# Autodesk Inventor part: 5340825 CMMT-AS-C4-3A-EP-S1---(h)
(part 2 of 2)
sketch "Sketch_51"
  geometry: L1 (0, 66.25)-(0, 58); L2 (1, 59)-(25.25, 59); L3 (28.25, 62)-(28.25, 85); L4 (28.25, 85)-(22, 85); L5 (22, 85)-(22, 65.5); L6 (21.75, 65.25)-(1, 65.25); A1 r 1 centre (1, 58) between (1, 59) and (0, 58); A2 r 3 centre (25.25, 62) between (25.25, 59) and (28.25, 62); A3 r 0.25 centre (21.75, 65.5) between (21.75, 65.25) and (22, 65.5); A4 r 1 centre (1, 66.25) between (0, 66.25) and (1, 65.25)
  constraints: 12 end point, 8 point on circle, 4 centre point
extrude "Extrusion63" cut sketch "Sketch_51" distance "d193" = 3.25; taper "d194" = 0 deg
sketch "Sketch_8"
  geometry: L1 (15, 101)-(5, 101); L2 (5, 101)-(5, 103); L3 (5, 103)-(7, 103); L4 (7, 103)-(7, 105.5); L5 (7, 105.5)-(8, 105.5); L6 (8, 105.5)-(8, 105); L7 (8, 105)-(10.133, 104.813); L8 (11.1, 101)-(5, 101); A1 r 8 centre (3.1, 101.001) between (11.1, 101) and (10.133, 104.813)
  constraints: 16 end point, 2 point on circle, 1 centre point
revolve "Revolution11" sketch "Sketch_8" stored, may be unused: angle "d195" = 360 deg
thread "Thread3" dims "d196" = 2, "d197" = 0
sketch "Sketch_9"
  geometry: A1 r 0.396 centre (-15.37, 100.209) between (-15.642, 100.497) and (-15.257, 99.83); A2 r 0.692 centre (-15.058, 99.167) between (-14.385, 99.327) and (-15.257, 99.83); A3 r 0.396 centre (-14, 99.418) between (-14.385, 99.327) and (-13.615, 99.327); A4 r 0.692 centre (-12.942, 99.167) between (-12.743, 99.83) and (-13.615, 99.327); A5 r 0.396 centre (-12.63, 100.209) between (-12.743, 99.83) and (-12.358, 100.497); A6 r 0.692 centre (-11.883, 101) between (-12.358, 101.503) and (-12.358, 100.497); A7 r 0.395 centre (-12.63, 101.791) between (-12.358, 101.503) and (-12.743, 102.17); A8 r 0.692 centre (-12.942, 102.833) between (-13.615, 102.673) and (-12.743, 102.17); A9 r 0.396 centre (-14, 102.582) between (-13.615, 102.673) and (-14.385, 102.673); A10 r 0.692 centre (-15.058, 102.833) between (-15.257, 102.17) and (-14.385, 102.673); A11 r 0.395 centre (-15.37, 101.791) between (-15.257, 102.17) and (-15.642, 101.503); A12 r 0.692 centre (-16.117, 101) between (-15.642, 100.497) and (-15.642, 101.503)
  constraints: 24 point on circle, 12 centre point
extrude "Extrusion64" cut sketch "Sketch_9" distance "d198" = 2; taper "d199" = 0 deg
sketch "Sketch_57"
  geometry: L1 (-16.27, 80.62)-(-16.27, 75.48); L2 (-15.77, 74.98)-(-13.63, 74.98); L3 (-13.13, 75.48)-(-13.13, 80.62); L4 (-13.63, 81.12)-(-15.77, 81.12); A1 r 0.5 centre (-15.77, 75.48) between (-16.27, 75.48) and (-15.77, 74.98); A2 r 0.5 centre (-13.63, 75.48) between (-13.63, 74.98) and (-13.13, 75.48); A3 r 0.5 centre (-13.63, 80.62) between (-13.13, 80.62) and (-13.63, 81.12); A4 r 0.5 centre (-15.77, 80.62) between (-15.77, 81.12) and (-16.27, 80.62)
  constraints: 8 end point, 8 point on circle, 4 centre point
extrude "Extrusion65" cut sketch "Sketch_57" distance "d200" = 2.5; taper "d201" = 0 deg
pattern_linear "Rectangular Pattern9" dims "d204" = 34.7, "d207" = 41.52024
sketch "Sketch_59"
  geometry: L1 (-1.792, 72.6)-(-1.792, 59.625); L2 (-1.292, 59.125)-(1.292, 59.125); L3 (1.792, 59.625)-(1.792, 72.6); L4 (1.292, 73.1)-(-1.292, 73.1); A1 r 0.5 centre (-1.292, 59.625) between (-1.792, 59.625) and (-1.292, 59.125); A2 r 0.5 centre (1.292, 59.625) between (1.292, 59.125) and (1.792, 59.625); A3 r 0.5 centre (1.292, 72.6) between (1.792, 72.6) and (1.292, 73.1); A4 r 0.5 centre (-1.292, 72.6) between (-1.292, 73.1) and (-1.792, 72.6)
  constraints: 8 end point, 8 point on circle, 4 centre point
extrude "Extrusion66" cut sketch "Sketch_59" distance "d208" = 4; taper "d209" = 0 deg
sketch "Sketch_61"
  geometry: L1 (148.738, -20)-(149.144, -20); L2 (149.144, -20)-(149.8, -19.031); L3 (149.8, -19.031)-(150.456, -20); L4 (150.456, -20)-(150.863, -20); L5 (150.863, -20)-(149.988, -18.719); L6 (149.988, -18.719)-(150.831, -17.5); L7 (150.831, -17.5)-(150.425, -17.5); L8 (150.425, -17.5)-(149.8, -18.438); L9 (149.8, -18.438)-(149.175, -17.5); L10 (149.175, -17.5)-(148.769, -17.5); L11 (148.769, -17.5)-(149.613, -18.719); L12 (149.613, -18.719)-(148.738, -20)
  constraints: 24 end point
extrude "Extrusion67" cut sketch "Sketch_61" distance "d210" = 2; taper "d211" = 0 deg
sketch "Sketch_60"
  geometry: L1 (146.625, -19.688)-(146.625, -20); L2 (146.625, -20)-(148.406, -20); L3 (148.406, -20)-(148.406, -17.5); L4 (148.406, -17.5)-(148.062, -17.5); L5 (148.062, -17.5)-(148.062, -18.625); L6 (148.062, -18.625)-(146.75, -18.625); L7 (146.75, -18.625)-(146.75, -18.938); L8 (146.75, -18.938)-(148.062, -18.938); L9 (148.062, -18.938)-(148.062, -19.688); L10 (148.062, -19.688)-(146.625, -19.688)
  constraints: 20 end point
extrude "Extrusion68" cut sketch "Sketch_60" distance "d212" = 2; taper "d213" = 0 deg
sketch "Pattern_13_SKETCH_1"
  geometry: L1 (131.938, -20)-(132.344, -20); L2 (132.344, -20)-(133, -19.031); L3 (133, -19.031)-(133.656, -20); L4 (133.656, -20)-(134.062, -20); L5 (134.062, -20)-(133.188, -18.719); L6 (133.188, -18.719)-(134.031, -17.5); L7 (134.031, -17.5)-(133.625, -17.5); L8 (133.625, -17.5)-(133, -18.438); L9 (133, -18.438)-(132.375, -17.5); L10 (132.375, -17.5)-(131.969, -17.5); L11 (131.969, -17.5)-(132.812, -18.719); L12 (132.812, -18.719)-(131.938, -20)
  constraints: 24 end point
sketch "Pattern_13_SKETCH_2"
  geometry: L1 (99.938, -20)-(100.344, -20); L2 (100.344, -20)-(101, -19.031); L3 (101, -19.031)-(101.656, -20); L4 (101.656, -20)-(102.062, -20); L5 (102.062, -20)-(101.188, -18.719); L6 (101.188, -18.719)-(102.031, -17.5); L7 (102.031, -17.5)-(101.625, -17.5); L8 (101.625, -17.5)-(101, -18.438); L9 (101, -18.438)-(100.375, -17.5); L10 (100.375, -17.5)-(99.969, -17.5); L11 (99.969, -17.5)-(100.812, -18.719); L12 (100.812, -18.719)-(99.938, -20)
  constraints: 24 end point
sketch "Pattern_13_SKETCH_3"
  geometry: L1 (98.937, 20)-(99.344, 20); L2 (99.344, 20)-(100, 20.969); L3 (100, 20.969)-(100.656, 20); L4 (100.656, 20)-(101.062, 20); L5 (101.062, 20)-(100.187, 21.281); L6 (100.187, 21.281)-(101.031, 22.5); L7 (101.031, 22.5)-(100.625, 22.5); L8 (100.625, 22.5)-(100, 21.562); L9 (100, 21.562)-(99.375, 22.5); L10 (99.375, 22.5)-(98.969, 22.5); L11 (98.969, 22.5)-(99.812, 21.281); L12 (99.812, 21.281)-(98.937, 20)
  constraints: 24 end point
sketch "Pattern_13_SKETCH_4"
  geometry: L1 (66.938, 20)-(67.344, 20); L2 (67.344, 20)-(68, 20.969); L3 (68, 20.969)-(68.656, 20); L4 (68.656, 20)-(69.062, 20); L5 (69.062, 20)-(68.188, 21.281); L6 (68.188, 21.281)-(69.031, 22.5); L7 (69.031, 22.5)-(68.625, 22.5); L8 (68.625, 22.5)-(68, 21.562); L9 (68, 21.562)-(67.375, 22.5); L10 (67.375, 22.5)-(66.969, 22.5); L11 (66.969, 22.5)-(67.812, 21.281); L12 (67.812, 21.281)-(66.938, 20)
  constraints: 24 end point
extrude "Extrusion69" cut sketch "Pattern_13_SKETCH_1" distance "d214" = 2; taper "d215" = 0 deg
extrude "Extrusion70" cut sketch "Pattern_13_SKETCH_2" distance "d216" = 2; taper "d217" = 0 deg
extrude "Extrusion71" cut sketch "Pattern_13_SKETCH_3" distance "d218" = 2; taper "d219" = 0 deg
extrude "Extrusion72" cut sketch "Pattern_13_SKETCH_4" distance "d220" = 2; taper "d221" = 0 deg
pattern_linear "Rectangular Pattern10" dims "d224" = 16.90625, "d227" = 0
sketch "Sketch_64"
  geometry: L1 (145, -17.85)-(145.325, -17.85); L2 (145.325, -17.85)-(145.325, -20); L3 (145.325, -20)-(145.675, -20); L4 (145.675, -20)-(146, -19.5); L5 (146, -19.5)-(146, -19); L6 (146, -19)-(145.675, -19.5); L7 (145.675, -19.5)-(145.675, -17.85); L8 (145.675, -17.85)-(146, -17.85); L9 (146, -17.85)-(146, -17.5); L10 (146, -17.5)-(145, -17.5); L11 (145, -17.5)-(145, -17.85)
  constraints: 22 end point
extrude "Extrusion73" cut sketch "Sketch_64" distance "d228" = 2; taper "d229" = 0 deg
sketch "Sketch_65"
  geometry: L1 (129.25, -19.25)-(128.9, -19.25); L2 (128.224, -18.96)-(129.25, -17.983); L3 (129.25, -17.983)-(129.25, -17.5); L4 (129.25, -17.5)-(127.75, -17.5); L5 (127.75, -17.5)-(127.75, -17.85); L6 (127.75, -17.85)-(128.882, -17.85); L7 (128.882, -17.85)-(127.983, -18.707); A1 r 0.75 centre (128.5, -19.25) between (127.983, -18.707) and (129.25, -19.25); A2 r 0.4 centre (128.5, -19.25) between (128.224, -18.96) and (128.9, -19.25)
  constraints: 14 end point, 4 point on circle, 2 centre point
extrude "Extrusion74" cut sketch "Sketch_65" distance "d230" = 2; taper "d231" = 0 deg
pattern_linear "Rectangular Pattern11" dims "d234" = 46.5, "d237" = 0
sketch "Sketch_67"
  geometry: L1 (95.875, -17.5)-(96.812, -20); L2 (96.812, -20)-(97.188, -20); L3 (97.188, -20)-(98.125, -17.5); L4 (98.125, -17.5)-(97.775, -17.5); L5 (97.775, -17.5)-(97.494, -18.25); L6 (97.494, -18.25)-(96.506, -18.25); L7 (96.506, -18.25)-(96.225, -17.5); L8 (96.225, -17.5)-(95.875, -17.5); L9 (96.623, -18.562)-(97, -19.567); L10 (97, -19.567)-(97.377, -18.562); L11 (97.377, -18.562)-(96.623, -18.562)
  constraints: 22 end point
extrude "Extrusion75" cut sketch "Sketch_67" distance "d238" = 2; taper "d239" = 0 deg
sketch "Sketch_68"
  geometry: L1 (97.915, 21.495)-(98.4, 22.5); L2 (98.4, 22.5)-(98.05, 22.5); L3 (98.05, 22.5)-(97.332, 21.091); C1 r 0.4 at (98, 20.75); A1 r 0.75 centre (98, 20.75) between (97.332, 21.091) and (97.915, 21.495); 1 further point
  constraints: 6 end point, 2 centre point, 2 point on circle
extrude "Extrusion76" cut sketch "Sketch_68" distance "d240" = 2; taper "d241" = 0 deg
pattern_linear "Rectangular Pattern12" dims "d244" = 40.0125, "d247" = 0
pattern_linear "Rectangular Pattern13" dims "d250" = 32.05, "d253" = 0
sketch "Sketch_71"
  geometry: L1 (63.688, 20)-(64.8, 20); L2 (64.8, 20)-(64.8, 22.5); L3 (64.8, 22.5)-(63.55, 22.5); L4 (63.688, 20.3)-(64.488, 20.3); L5 (64.488, 20.3)-(64.488, 21); L6 (64.488, 21)-(63.688, 21); L7 (63.55, 21.3)-(64.488, 21.3); L8 (64.488, 21.3)-(64.488, 22.2); L9 (64.488, 22.2)-(63.55, 22.2); A1 r 0.75 centre (63.55, 21.75) between (63.55, 22.5) and (63.204, 21.085); A2 r 0.65 centre (63.688, 20.65) between (63.204, 21.085) and (63.688, 20); A3 r 0.35 centre (63.688, 20.65) between (63.688, 21) and (63.688, 20.3); A4 r 0.45 centre (63.55, 21.75) between (63.55, 22.2) and (63.55, 21.3)
  constraints: 18 end point, 8 point on circle, 4 centre point
extrude "Extrusion77" cut sketch "Sketch_71" distance "d254" = 2; taper "d255" = 0 deg
sketch "Sketch_72"
  geometry: L1 (-22.562, 59)-(-22.156, 59); L2 (-22.156, 59)-(-21.5, 59.969); L3 (-21.5, 59.969)-(-20.844, 59); L4 (-20.844, 59)-(-20.438, 59); L5 (-20.438, 59)-(-21.312, 60.281); L6 (-21.312, 60.281)-(-20.469, 61.5); L7 (-20.469, 61.5)-(-20.875, 61.5); L8 (-20.875, 61.5)-(-21.5, 60.562); L9 (-21.5, 60.562)-(-22.125, 61.5); L10 (-22.125, 61.5)-(-22.531, 61.5); L11 (-22.531, 61.5)-(-21.688, 60.281); L12 (-21.688, 60.281)-(-22.562, 59)
  constraints: 24 end point
extrude "Extrusion78" cut sketch "Sketch_72" distance "d256" = 0.5; taper "d257" = 0 deg
sketch "Sketch_73"
  geometry: L1 (-20.285, 60.345)-(-19.954, 60.225); L2 (-19.954, 60.225)-(-19.857, 60.225); L3 (-19.968, 59.7)-(-20.281, 59.481); L4 (-19.842, 60.68)-(-19.726, 61.15); L5 (-19.726, 61.15)-(-18.75, 61.15); L6 (-18.75, 61.15)-(-18.75, 61.5); L7 (-18.75, 61.5)-(-20, 61.5); L8 (-20, 61.5)-(-20.285, 60.345); A1 r 0.5 centre (-19.5, 59.875) between (-19.968, 59.7) and (-19.857, 60.225); A2 r 0.875 centre (-19.5, 59.875) between (-20.281, 59.481) and (-19.842, 60.68)
  constraints: 16 end point, 4 point on circle, 2 centre point
extrude "Extrusion79" cut sketch "Sketch_73" distance "d258" = 0.5; taper "d259" = 0 deg
sketch "Sketch_74"
  geometry: L1 (-1.701, 27.5)-(-1.433, 27.5); L2 (-1.433, 27.5)-(-1, 28.139); L3 (-1, 28.139)-(-0.567, 27.5); L4 (-0.567, 27.5)-(-0.299, 27.5); L5 (-0.299, 27.5)-(-0.876, 28.346); L6 (-0.876, 28.346)-(-0.319, 29.15); L7 (-0.319, 29.15)-(-0.588, 29.15); L8 (-0.588, 29.15)-(-1, 28.531); L9 (-1, 28.531)-(-1.413, 29.15); L10 (-1.413, 29.15)-(-1.681, 29.15); L11 (-1.681, 29.15)-(-1.124, 28.346); L12 (-1.124, 28.346)-(-1.701, 27.5)
  constraints: 24 end point
extrude "Extrusion80" cut sketch "Sketch_74" distance "d260" = 0.5; taper "d261" = 0 deg
sketch "Sketch_75"
  geometry: L1 (-0.13, 27.731)-(-0.13, 27.5); L2 (-0.13, 27.5)-(0.53, 27.5); L3 (0.53, 27.5)-(0.53, 27.731); L4 (0.53, 27.731)-(0.316, 27.731); L5 (0.316, 27.731)-(0.316, 29.15); L6 (0.316, 29.15)-(0.085, 29.15); L7 (0.085, 29.15)-(-0.13, 28.82); L8 (-0.13, 28.82)-(-0.13, 28.49); L9 (-0.13, 28.49)-(0.085, 28.82); L10 (0.085, 28.82)-(0.085, 27.731); L11 (0.085, 27.731)-(-0.13, 27.731)
  constraints: 22 end point
extrude "Extrusion81" cut sketch "Sketch_75" distance "d262" = 0.5; taper "d263" = 0 deg
sketch "Sketch_76"
  geometry: C1 r 0.214 at (1.2, 28.738); C2 r 0.264 at (1.2, 27.995); A1 r 0.495 centre (1.2, 27.995) between (0.941, 28.417) and (1.459, 28.417); A2 r 0.412 centre (1.2, 28.738) between (1.459, 28.417) and (0.941, 28.417); 2 further points
  constraints: 4 centre point, 4 point on circle
extrude "Extrusion82" cut sketch "Sketch_76" distance "d264" = 0.5; taper "d265" = 0 deg
sketch "Pattern_18_SKETCH_1"
  geometry: L1 (-1.701, 11)-(-1.433, 11); L2 (-1.433, 11)-(-1, 11.639); L3 (-1, 11.639)-(-0.567, 11); L4 (-0.567, 11)-(-0.299, 11); L5 (-0.299, 11)-(-0.876, 11.846); L6 (-0.876, 11.846)-(-0.319, 12.65); L7 (-0.319, 12.65)-(-0.588, 12.65); L8 (-0.588, 12.65)-(-1, 12.031); L9 (-1, 12.031)-(-1.413, 12.65); L10 (-1.413, 12.65)-(-1.681, 12.65); L11 (-1.681, 12.65)-(-1.124, 11.846); L12 (-1.124, 11.846)-(-1.701, 11)
  constraints: 24 end point
sketch "Pattern_18_SKETCH_2"
  geometry: L1 (-1.701, -8)-(-1.433, -8); L2 (-1.433, -8)-(-1, -7.361); L3 (-1, -7.361)-(-0.567, -8); L4 (-0.567, -8)-(-0.299, -8); L5 (-0.299, -8)-(-0.876, -7.154); L6 (-0.876, -7.154)-(-0.319, -6.35); L7 (-0.319, -6.35)-(-0.588, -6.35); L8 (-0.588, -6.35)-(-1, -6.969); L9 (-1, -6.969)-(-1.413, -6.35); L10 (-1.413, -6.35)-(-1.681, -6.35); L11 (-1.681, -6.35)-(-1.124, -7.154); L12 (-1.124, -7.154)-(-1.701, -8)
  constraints: 24 end point
sketch "Pattern_18_SKETCH_3"
  geometry: L1 (-1.701, -24)-(-1.433, -24); L2 (-1.433, -24)-(-1, -23.361); L3 (-1, -23.361)-(-0.567, -24); L4 (-0.567, -24)-(-0.299, -24); L5 (-0.299, -24)-(-0.876, -23.154); L6 (-0.876, -23.154)-(-0.319, -22.35); L7 (-0.319, -22.35)-(-0.588, -22.35); L8 (-0.588, -22.35)-(-1, -22.969); L9 (-1, -22.969)-(-1.413, -22.35); L10 (-1.413, -22.35)-(-1.681, -22.35); L11 (-1.681, -22.35)-(-1.124, -23.154); L12 (-1.124, -23.154)-(-1.701, -24)
  constraints: 24 end point
sketch "Pattern_18_SKETCH_4"
  geometry: L1 (18.299, 27.5)-(18.567, 27.5); L2 (18.567, 27.5)-(19, 28.139); L3 (19, 28.139)-(19.433, 27.5); L4 (19.433, 27.5)-(19.701, 27.5); L5 (19.701, 27.5)-(19.124, 28.346); L6 (19.124, 28.346)-(19.681, 29.15); L7 (19.681, 29.15)-(19.412, 29.15); L8 (19.412, 29.15)-(19, 28.531); L9 (19, 28.531)-(18.587, 29.15); L10 (18.587, 29.15)-(18.319, 29.15); L11 (18.319, 29.15)-(18.876, 28.346); L12 (18.876, 28.346)-(18.299, 27.5)
  constraints: 24 end point
sketch "Pattern_18_SKETCH_5"
  geometry: L1 (18.299, 7.5)-(18.567, 7.5); L2 (18.567, 7.5)-(19, 8.139); L3 (19, 8.139)-(19.433, 7.5); L4 (19.433, 7.5)-(19.701, 7.5); L5 (19.701, 7.5)-(19.124, 8.346); L6 (19.124, 8.346)-(19.681, 9.15); L7 (19.681, 9.15)-(19.412, 9.15); L8 (19.412, 9.15)-(19, 8.531); L9 (19, 8.531)-(18.587, 9.15); L10 (18.587, 9.15)-(18.319, 9.15); L11 (18.319, 9.15)-(18.876, 8.346); L12 (18.876, 8.346)-(18.299, 7.5)
  constraints: 24 end point
sketch "Pattern_18_SKETCH_6"
  geometry: L1 (18.299, -12.5)-(18.567, -12.5); L2 (18.567, -12.5)-(19, -11.861); L3 (19, -11.861)-(19.433, -12.5); L4 (19.433, -12.5)-(19.701, -12.5); L5 (19.701, -12.5)-(19.124, -11.654); L6 (19.124, -11.654)-(19.681, -10.85); L7 (19.681, -10.85)-(19.412, -10.85); L8 (19.412, -10.85)-(19, -11.469); L9 (19, -11.469)-(18.587, -10.85); L10 (18.587, -10.85)-(18.319, -10.85); L11 (18.319, -10.85)-(18.876, -11.654); L12 (18.876, -11.654)-(18.299, -12.5)
  constraints: 24 end point
extrude "Extrusion83" cut sketch "Pattern_18_SKETCH_1" distance "d266" = 0.5; taper "d267" = 0 deg
extrude "Extrusion84" cut sketch "Pattern_18_SKETCH_2" distance "d268" = 0.5; taper "d269" = 0 deg
extrude "Extrusion85" cut sketch "Pattern_18_SKETCH_3" distance "d270" = 0.5; taper "d271" = 0 deg
extrude "Extrusion86" cut sketch "Pattern_18_SKETCH_4" distance "d272" = 0.5; taper "d273" = 0 deg
extrude "Extrusion87" cut sketch "Pattern_18_SKETCH_5" distance "d274" = 0.5; taper "d275" = 0 deg
extrude "Extrusion88" cut sketch "Pattern_18_SKETCH_6" distance "d276" = 0.5; taper "d277" = 0 deg
pattern_linear "Rectangular Pattern14" dims "d280" = 20.05, "d283" = 16.5
sketch "Sketch_79"
  geometry: L1 (1.695, 11.495)-(1.695, 12.155); L2 (0.705, 12.155)-(0.705, 11.495); L3 (1.464, 11.495)-(1.464, 12.155); L4 (0.936, 12.155)-(0.936, 11.495); A1 r 0.495 centre (1.2, 11.495) between (0.705, 11.495) and (1.695, 11.495); A2 r 0.495 centre (1.2, 12.155) between (1.695, 12.155) and (0.705, 12.155); A3 r 0.264 centre (1.2, 11.495) between (0.936, 11.495) and (1.464, 11.495); A4 r 0.264 centre (1.2, 12.155) between (1.464, 12.155) and (0.936, 12.155)
  constraints: 8 end point, 8 point on circle, 4 centre point
extrude "Extrusion89" cut sketch "Sketch_79" distance "d284" = 0.5; taper "d285" = 0 deg
sketch "Sketch_80"
  geometry: L1 (-0.195, -6.845)-(0.036, -6.845); L2 (0.329, -7.06)-(0.251, -7.06); L3 (0.251, -7.06)-(0.251, -7.29); L4 (0.251, -7.29)-(0.329, -7.29); L5 (0.036, -7.505)-(-0.195, -7.505); A1 r 0.495 centre (0.3, -7.505) between (-0.195, -7.505) and (0.669, -7.175); A2 r 0.495 centre (0.3, -6.845) between (0.669, -7.175) and (-0.195, -6.845); A3 r 0.264 centre (0.3, -6.845) between (0.529, -6.713) and (0.036, -6.845); A4 r 0.231 centre (0.329, -6.829) between (0.329, -7.06) and (0.529, -6.713); A5 r 0.231 centre (0.329, -7.522) between (0.529, -7.637) and (0.329, -7.29); A6 r 0.264 centre (0.3, -7.505) between (0.036, -7.505) and (0.529, -7.637)
  constraints: 12 point on circle, 10 end point, 6 centre point
extrude "Extrusion90" cut sketch "Sketch_80" distance "d286" = 0.5; taper "d287" = 0 deg
sketch "Sketch_81"
  geometry: L1 (-0.195, -22.845)-(0.036, -22.845); L2 (0.482, -23.036)-(-0.195, -23.681); L3 (-0.195, -23.681)-(-0.195, -24); L4 (-0.195, -24)-(0.795, -24); L5 (0.795, -24)-(0.795, -23.769); L6 (0.795, -23.769)-(0.048, -23.769); L7 (0.048, -23.769)-(0.641, -23.203); A1 r 0.264 centre (0.3, -22.845) between (0.482, -23.036) and (0.036, -22.845); A2 r 0.495 centre (0.3, -22.845) between (0.641, -23.203) and (-0.195, -22.845)
  constraints: 14 end point, 4 point on circle, 2 centre point
extrude "Extrusion91" cut sketch "Sketch_81" distance "d288" = 0.5; taper "d289" = 0 deg
sketch "Sketch_82"
  geometry: L1 (22.259, 28.16)-(22.028, 28.16); L2 (20.972, 28.231)-(20.972, 28.419); L3 (22.028, 28.49)-(22.25, 28.537); L4 (20.741, 28.49)-(20.741, 28.16); A1 r 0.769 centre (21.5, 28.283) between (20.741, 28.16) and (22.259, 28.16); A2 r 0.561 centre (21.5, 28.35) between (21.019, 28.061) and (22.028, 28.16); A3 r 0.33 centre (21.302, 28.231) between (20.972, 28.231) and (21.019, 28.061); A4 r 0.33 centre (21.302, 28.419) between (21.019, 28.589) and (20.972, 28.419); A5 r 0.561 centre (21.5, 28.3) between (22.028, 28.49) and (21.019, 28.589); A6 r 0.769 centre (21.5, 28.367) between (22.25, 28.537) and (20.741, 28.49)
  constraints: 12 point on circle, 8 end point, 6 centre point
extrude "Extrusion92" cut sketch "Sketch_82" distance "d290" = 0.5; taper "d291" = 0 deg
sketch "Sketch_83"
  geometry: L1 (20.514, 8.919)-(20.63, 8.919); L2 (20.63, 8.919)-(20.63, 9.15); L3 (20.63, 9.15)-(20.497, 9.15); L4 (19.755, 8.408)-(19.755, 7.995); C1 r 0.264 at (20.25, 7.995); A1 r 0.495 centre (20.25, 7.995) between (19.755, 7.995) and (19.987, 8.414); A2 r 0.528 centre (20.514, 8.391) between (20.514, 8.919) and (19.987, 8.414); A3 r 0.743 centre (20.498, 8.407) between (20.497, 9.15) and (19.755, 8.408); 1 further point
  constraints: 8 end point, 6 point on circle, 4 centre point
extrude "Extrusion93" cut sketch "Sketch_83" distance "d292" = 0.5; taper "d293" = 0 deg
sketch "Sketch_84"
  geometry: L1 (20.94, 9.15)-(20.94, 7.5); L2 (20.94, 7.5)-(21.765, 7.5); L3 (21.674, 9.15)-(20.94, 9.15); L4 (21.146, 8.952)-(21.146, 8.49); L5 (21.146, 8.49)-(21.674, 8.49); L6 (21.674, 8.952)-(21.146, 8.952); L7 (21.146, 7.698)-(21.765, 7.698); L8 (21.765, 8.292)-(21.146, 8.292); L9 (21.146, 8.292)-(21.146, 7.698); A1 r 0.495 centre (21.765, 7.995) between (21.765, 7.5) and (21.993, 8.434); A2 r 0.429 centre (21.674, 8.721) between (21.993, 8.434) and (21.674, 9.15); A3 r 0.231 centre (21.674, 8.721) between (21.674, 8.49) and (21.674, 8.952); A4 r 0.297 centre (21.765, 7.995) between (21.765, 7.698) and (21.765, 8.292)
  constraints: 18 end point, 8 point on circle, 4 centre point
extrude "Extrusion94" cut sketch "Sketch_84" distance "d294" = 0.5; taper "d295" = 0 deg
pattern_linear "Rectangular Pattern15" dims "d298" = 20, "d301" = 0
sketch "Sketch_86"
  geometry: L1 (20.758, -12.5)-(20.989, -12.5); L2 (20.989, -12.5)-(21.174, -12.005); L3 (21.174, -12.005)-(21.826, -12.005); L4 (21.826, -12.005)-(22.012, -12.5); L5 (22.012, -12.5)-(22.242, -12.5); L6 (22.242, -12.5)-(21.624, -10.85); L7 (21.624, -10.85)-(21.376, -10.85); L8 (21.376, -10.85)-(20.758, -12.5); L9 (21.251, -11.799)-(21.749, -11.799); L10 (21.749, -11.799)-(21.5, -11.136); L11 (21.5, -11.136)-(21.251, -11.799)
  constraints: 22 end point
extrude "Extrusion95" cut sketch "Sketch_86" distance "d302" = 0.5; taper "d303" = 0 deg
sketch "Sketch108"
  geometry: 1 further point
hole "Hole2" sketch "Sketch108" at (-14, 91) diameter "d304" = 9; stored, may be unused: countersink angle "d308" = 90 deg, drill point angle "d310" = 0 deg; dims "d305" = 6, "d306" = 4, "d307" = 2, "d309" = 0.5
sketch "Sketch_88"
  geometry: L1 (-15.78, 87.79)-(-11.97, 87.79); L2 (-11.97, 87.79)-(-11.97, 88.09); L3 (-11.97, 88.09)-(-15.78, 88.09); L4 (-15.78, 88.09)-(-15.78, 87.79); L5 (-16.89, 88.94)-(-11.12, 88.94); L6 (-11.12, 88.94)-(-11.12, 89.24); L7 (-11.12, 89.24)-(-16.89, 89.24); L8 (-16.89, 89.24)-(-16.89, 88.94); L9 (-17.67, 90.05)-(-10.38, 90.05); L10 (-10.38, 90.05)-(-10.38, 90.35); L11 (-10.38, 90.35)-(-13.75, 90.35); L12 (-13.75, 90.35)-(-13.75, 94.83); L13 (-13.75, 94.83)-(-14.05, 94.83); L14 (-14.05, 94.83)-(-14.05, 90.35); L15 (-14.05, 90.35)-(-17.67, 90.35); L16 (-17.67, 90.35)-(-17.67, 90.05); C1 r 4.35 at (-14, 91); 1 further point
  constraints: 32 end point, 1 centre point
extrude "Extrusion96" join sketch "Sketch_88" distance "d311" = 0.5; taper "d312" = 0 deg
sketch "Sketch_89"
  geometry: L1 (-16, 22)-(-16, -22); L2 (-16, -22)-(70, -22); L3 (70, -22)-(70, 22); L4 (70, 22)-(-16, 22)
  constraints: 8 end point
extrude "Extrusion97" cut sketch "Sketch_89" distance "d313" = 10; taper "d314" = 0 deg
sketch "Sketch_90"
  geometry: L1 (10, -16)-(10, 16); L2 (2, 16)-(2, -16); A1 r 4 centre (6, -16) between (2, -16) and (10, -16); A2 r 4 centre (6, 16) between (10, 16) and (2, 16)
  constraints: 4 end point, 4 point on circle, 2 centre point
extrude "Extrusion98" join sketch "Sketch_90" distance "d315" = 80; taper "d316" = 0 deg
sketch "Sketch_91"
  geometry: L1 (57, -10)-(64.5, -10); L2 (64.5, -10)-(64.5, 10); L3 (64.5, 10)-(57, 10); A1 r 10 centre (57, 0) between (57, 10) and (57, -10)
  constraints: 6 end point, 2 point on circle, 1 centre point
extrude "Extrusion99" cut sketch "Sketch_91" distance "d317" = 9.5; taper "d318" = 0 deg
sketch "Sketch_92"
  geometry: L1 (-8, 10)-(-15.5, 10); L2 (-15.5, 10)-(-15.5, -10); L3 (-15.5, -10)-(-8, -10); A1 r 10 centre (-8, 0) between (-8, -10) and (-8, 10)
  constraints: 6 end point, 2 point on circle, 1 centre point
extrude "Extrusion100" cut sketch "Sketch_92" distance "d319" = 9.5; taper "d320" = 0 deg
sketch "Sketch_93"
  geometry: L1 (9.5, 57)-(4.05, 57); L2 (4.05, 57)-(4.05, 60.1); L3 (4.45, 60.5)-(8.1, 60.5); L4 (8.1, 60.5)-(8.1, 60.9); L5 (8.1, 60.9)-(9.5, 60.9); L6 (9.5, 60.9)-(9.5, 57); L7 (9.5, 57)-(4.05, 57); A1 r 0.4 centre (4.45, 60.1) between (4.45, 60.5) and (4.05, 60.1)
  constraints: 14 end point, 2 point on circle, 1 centre point
revolve "Revolution12" sketch "Sketch_93" stored, may be unused: angle "d321" = 360 deg
pattern_linear "Rectangular Pattern16" dims "d324" = 65, "d327" = 0
sketch "Sketch_95"
  geometry: L1 (56.134, 1.5)-(55.268, 0); L2 (55.268, 0)-(56.134, -1.5); L3 (56.134, -1.5)-(57.866, -1.5); L4 (57.866, -1.5)-(58.732, 0); L5 (58.732, 0)-(57.866, 1.5); L6 (57.866, 1.5)-(56.134, 1.5)
  constraints: 12 end point
extrude "Extrusion101" cut sketch "Sketch_95" distance "d328" = 6.05; taper "d329" = 0 deg
pattern_linear "Rectangular Pattern17" dims "d332" = 65, "d335" = 0
sketch "Sketch_97"
  geometry: L1 (5, 16)-(7, 16); C1 r 1.5 at (6, 13); 1 further point
  constraints: 2 end point, 1 centre point
revolve "Revolution13" sketch "Sketch_97" stored, may be unused: angle "d336" = 90 deg
sketch "Sketch_98"
  geometry: L1 (5, -10)-(7, -10); C1 r 1.5 at (6, -13); 1 further point
  constraints: 2 end point, 1 centre point
revolve "Revolution14" sketch "Sketch_98" stored, may be unused: angle "d337" = 90 deg
node "ANBAU_XY"
node "ANBAU_YZ"
node "ANBAU_ZX"
node "ANBAU_X"
node "ANBAU_Y"
node "ANBAU_Z"
node "ANBAU_Center"
node "CLAMP_XY"
node "CLAMP_YZ"
node "CLAMP_ZX"
node "CLAMP_X"
node "CLAMP_Y"
node "CLAMP_Z"
node "CLAMP_Center"
node "COVER_XY"
node "COVER_YZ"
node "COVER_ZX"
node "COVER_X"
node "COVER_Y"
node "COVER_Z"
node "COVER_Center"
node "PLUG_XY"
node "PLUG_YZ"
node "PLUG_ZX"
node "PLUG_X"
node "PLUG_Y"
node "PLUG_Z"
node "PLUG_Center"
body "Solid1"
pattern_linear "Rectangular Pattern4" dims "d60" = 3.5, "d63" = 8.25
pattern_linear "Rectangular Pattern5" dims "d92" = 3.5, "d95" = 8.25
other parameters: "d338" = 0
